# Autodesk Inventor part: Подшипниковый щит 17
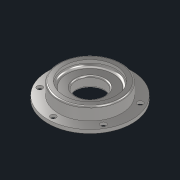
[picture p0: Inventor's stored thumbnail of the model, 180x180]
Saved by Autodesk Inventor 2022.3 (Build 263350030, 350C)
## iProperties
Created: 2022-08
Part Number: Подшипниковый щит 17
Material: Сталь 40ХНМА
Document SubType Name: Modeling
Designer: Карташов
Density: 7.85 g/cm^3
Appearance: С умеренной полировкой
Author: Карташов
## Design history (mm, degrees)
sketch "Эскиз1"
  geometry: L1 (0, 0)-(0, 34.001); L2 (22, 0)-(60, 0); L3 (60, 0)-(60, 5); L4 (60, 5)-(45, 5); L5 (45, 5)-(45, 21); L6 (43, 23)-(37, 23); L7 (37, 23)-(37, 18.76); L8 (33, 14.76)-(22, 14.76); L9 (20, 12.76)-(20, 2); A1 r 4 centre (33, 18.76) between (33, 14.76) and (37, 18.76); A2 r 2 centre (22, 12.76) between (22, 14.76) and (20, 12.76); A3 r 2 centre (22, 2) between (20, 2) and (22, 0); A4 r 2 centre (43, 21) between (45, 21) and (43, 23); 2 further points
  constraints: 18 end point, 8 point on circle, 8 tangent, 4 centre point, 4 horizontal, 4 vertical, 2 equal radius, 2 point on line, 1 horizontal alignment, 1 midpoint, 1 perpendicular
  dimensions: "d0" = 90 diameter of L5 point (0, 17); "d1" = 120 diameter of L3 L1; "d2" = 40 diameter of L9 L1; "d3" = 23 vertical distance of L2.end point (45, 23); "d4" = 5 distance of L2.end L3.end; "d5" = 8.24 distance between parallel lines of L8 L6; "d6" = 8 distance of point (45, 23) L6.end; "d7" = 4 radius of A1; "d8" = 2 radius of A2
revolve "Вращение1" sketch "Эскиз1" stored, may be unused: angle "d9" = 90 deg
sketch "Эскиз2"
  geometry: C1 r 45 at (0, 0) reference; C2 r 60 at (0, 0) reference; 2 further points
  constraints: 1 vertical alignment
  dimensions: "d10" = 52.5 distance of point (0, 0) point (0, -52.5)
  node "Спроецированная петля1"
sketch "Эскиз3"
  geometry: 2 further points
hole "Отверстие1" sketch "Эскиз3" at (0, 52.5) diameter "d11" = 8; stored, may be unused: countersink angle "d15" = 90 deg, drill point angle "d17" = 0 deg; dims "d12" = 6, "d13" = 13, "d14" = 1, "d16" = 22.5
pattern_circular "Круговой массив1" dims angle "d19" = 360 deg
node "Твердое тело1"
